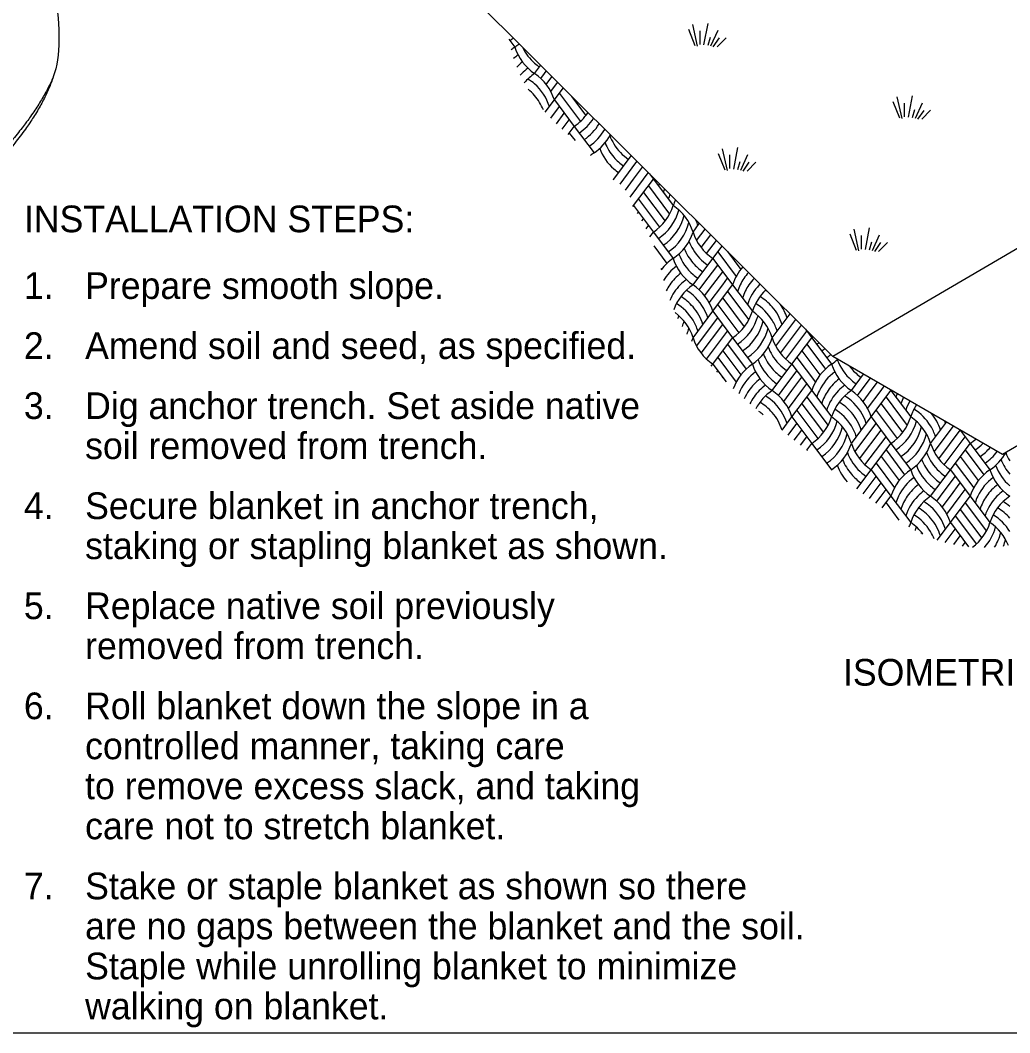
# Model space of a CAD drawing. Extents: x 99862 to 103151, y 100000 to 102076.
# Drawn here: x 100962 to 101704, y 100000 to 100758 of the extents above; entities that cross this region are included whole.
import ezdxf

# ---------------------------------------------------------------- set-up
doc = ezdxf.new("R2010")
doc.units = 0
for name, color, linetype in [('Level 1', 7, 'Continuous'), ('Level 2', 7, 'Continuous'), ('Level 20', 7, 'Continuous'), ('Level 3', 7, 'Continuous'), ('Level 31', 7, 'Continuous')]:
    doc.layers.add(name, color=color, linetype=linetype)

msp = doc.modelspace()

# ---------------------------------------------------------------- linework, layer by layer
at = {"layer": 'Level 1'}
for p, q in [((102742.49, 101035.83), (101698.37, 100433.01)), ((102103.79, 100817.24), (101571.09, 100506.49))]:
    msp.add_line(p, q, dxfattribs=at)
msp.add_lwpolyline([(99862, 99999.5), (103151, 99999.5), (103151, 102075.5), (99862, 102075.5)], close=True, dxfattribs=at)
for points in [[(100787.82, 101286.48), (101571.09, 100506.49)], [(101698.37, 100433.01), (101571.09, 100506.49)]]:
    msp.add_lwpolyline(points, dxfattribs=at)
at = {"layer": 'Level 2'}
for points, degree in [([(100901.77, 101124.83), (101009.66, 100986.39), (100961.48, 100855.3), (100998.83, 100747.61), (100986.43, 100715.92)], 3), ([(100986.43, 100715.92), (100969.49, 100664.49), (100884.41, 100595.03)], 2), ([(100986.42, 100715.89), (100965.62, 100667.43), (100887.77, 100603.87)], 2)]:
    msp.add_open_spline(points, degree=degree, dxfattribs=at)
at = {"layer": 'Level 3'}
for p, q in [((101328.27, 100744.14), (101332.66, 100738.27)), ((101347.51, 100718.47), (101352, 100724.45)), ((101354.94, 100718.47), (101356.25, 100720.22)), ((101352.17, 100714.78), (101354.94, 100718.47)), ((101356.24, 100710.32), (101360.5, 100715.99)), ((101359.69, 100705.01), (101364.75, 100711.76)), ((101362.36, 100698.67), (101369, 100707.53)), ((101366.08, 100703.62), (101381.87, 100682.57)), ((101355.54, 100689.57), (101362.36, 100698.67)), ((101362.36, 100698.67), (101377.21, 100678.87)), ((101375.17, 100701.4), (101385.94, 100687.03)), ((101359.63, 100685.13), (101366.08, 100693.72)), ((101363.86, 100680.87), (101369.79, 100688.77)), ((101368.22, 100676.79), (101373.5, 100683.82)), ((101372.65, 100672.8), (101377.21, 100678.87)), ((101373.5, 100673.92), (101377.81, 100668.18)), ((101377.21, 100678.87), (101392.06, 100659.08)), ((101406.91, 100639.28), (101420.03, 100656.77)), ((101414.34, 100639.28), (101424.28, 100652.54)), ((101421.76, 100639.28), (101428.53, 100648.31)), ((101429.18, 100639.28), (101432.79, 100644.08)), ((101433.66, 100643.21), (101436.61, 100639.28)), ((101411.56, 100635.58), (101414.34, 100639.28)), ((101415.64, 100631.12), (101421.76, 100639.28)), ((101419.09, 100625.81), (101429.18, 100639.28)), ((101421.76, 100619.48), (101436.61, 100639.28)), ((101436.61, 100639.28), (101451.46, 100619.48)), ((101429.18, 100629.38), (101445.34, 100607.84)), ((101432.9, 100634.33), (101448.78, 100613.14)), ((101425.47, 100624.43), (101441.26, 100603.37)), ((101421.27, 100618.83), (101421.76, 100619.48)), ((101421.76, 100619.48), (101436.61, 100599.68)), ((101424.7, 100613.5), (101425.47, 100614.53)), ((101427.98, 100607.97), (101429.18, 100609.58)), ((101466.31, 100599.68), (101471.05, 100606.01)), ((101431.08, 100602.2), (101432.9, 100604.63)), ((101433.99, 100596.19), (101436.61, 100599.68)), ((101436.61, 100599.68), (101451.46, 100579.88)), ((101468.98, 100593.34), (101475.31, 100601.78)), ((101472.43, 100588.04), (101479.56, 100597.55)), ((101476.5, 100583.57), (101483.81, 100593.32)), ((101436.91, 100589.38), (101446.8, 100576.19)), ((101481.16, 100579.88), (101488.06, 100589.09)), ((101484.87, 100584.83), (101498.68, 100566.41)), ((101492.15, 100585.03), (101502.12, 100571.72)), ((101466.31, 100560.08), (101481.16, 100579.88)), ((101473.73, 100560.08), (101484.87, 100574.93)), ((101481.16, 100579.88), (101496.01, 100560.08)), ((101442.2, 100572.42), (101442.73, 100571.72)), ((101481.16, 100560.08), (101488.58, 100569.98)), ((101470.96, 100556.39), (101473.73, 100560.08)), ((101475.04, 100551.92), (101481.16, 100560.08)), ((101478.48, 100546.61), (101488.58, 100560.08)), ((101481.16, 100540.28), (101496.01, 100560.08)), ((101488.58, 100560.08), (101492.29, 100565.03)), ((101496.01, 100560.08), (101510.86, 100540.28)), ((101492.29, 100555.13), (101508.18, 100533.95)), ((101484.87, 100545.23), (101500.66, 100524.18)), ((101488.58, 100550.18), (101504.74, 100528.64)), ((101466.31, 100520.48), (101481.16, 100540.28)), ((101481.16, 100540.28), (101496.01, 100520.48)), ((101525.7, 100520.48), (101539.09, 100538.33)), ((101468.98, 100514.15), (101484.87, 100535.33)), ((101472.43, 100508.84), (101488.58, 100530.38)), ((101528.38, 100514.15), (101543.34, 100534.1)), ((101531.82, 100508.84), (101547.59, 100529.87)), ((101476.5, 100504.38), (101492.29, 100525.43)), ((101535.9, 100504.38), (101551.69, 100525.43)), ((101550.64, 100526.84), (101555.4, 100520.48)), ((101481.16, 100500.68), (101496.01, 100520.48)), ((101492.29, 100515.53), (101506.2, 100496.99)), ((101496.01, 100520.48), (101510.86, 100500.68)), ((101540.55, 100500.68), (101555.4, 100520.48)), ((101551.69, 100515.53), (101565.6, 100496.99)), ((101555.4, 100520.48), (101570.25, 100500.68)), ((101488.58, 100510.58), (101502.12, 100492.53)), ((101547.98, 100510.58), (101561.52, 100492.53)), ((101480.05, 100499.2), (101481.16, 100500.68)), ((101481.16, 100500.68), (101491.07, 100487.46)), ((101484.87, 100505.63), (101498.68, 100487.22)), ((101525.7, 100480.88), (101540.55, 100500.68)), ((101540.55, 100500.68), (101555.4, 100480.88)), ((101544.27, 100505.63), (101558.08, 100487.22)), ((101484.11, 100494.72), (101484.87, 100495.73)), ((101533.13, 100480.88), (101544.27, 100495.73)), ((101585.1, 100480.88), (101594.27, 100493.11)), ((101488.24, 100490.33), (101488.58, 100490.78)), ((101540.55, 100480.88), (101547.98, 100490.78)), ((101547.98, 100480.88), (101551.69, 100485.83)), ((101592.53, 100480.88), (101599.45, 100490.12)), ((101599.95, 100480.88), (101604.63, 100487.13)), ((101607.38, 100480.88), (101609.81, 100484.13)), ((101530.36, 100477.19), (101533.13, 100480.88)), ((101534.44, 100472.73), (101540.55, 100480.88)), ((101537.88, 100467.42), (101547.98, 100480.88)), ((101540.55, 100461.09), (101555.4, 100480.88)), ((101551.69, 100475.93), (101567.58, 100454.75)), ((101555.4, 100480.88), (101570.25, 100461.09)), ((101589.76, 100477.19), (101592.53, 100480.88)), ((101593.83, 100472.73), (101599.95, 100480.88)), ((101597.28, 100467.42), (101607.38, 100480.88)), ((101599.95, 100461.09), (101614.8, 100480.88)), ((101611.09, 100475.93), (101626.97, 100454.75)), ((101614.31, 100481.54), (101614.8, 100480.88)), ((101614.8, 100480.88), (101629.65, 100461.09)), ((101547.98, 100470.98), (101564.13, 100449.44)), ((101607.38, 100470.98), (101623.53, 100449.44)), ((101533.07, 100451.1), (101540.55, 100461.09)), ((101540.55, 100461.09), (101555.4, 100441.29)), ((101544.27, 100466.04), (101560.06, 100444.98)), ((101585.1, 100441.29), (101599.95, 100461.09)), ((101599.95, 100461.09), (101614.8, 100441.29)), ((101603.66, 100466.04), (101619.45, 100444.98)), ((101537.68, 100447.35), (101544.27, 100456.14)), ((101587.78, 100434.95), (101603.66, 100456.14)), ((101644.5, 100441.29), (101656.44, 100457.21)), ((101647.17, 100434.95), (101661.62, 100454.22)), ((101542.29, 100443.6), (101547.98, 100451.19)), ((101546.93, 100439.89), (101551.69, 100446.24)), ((101591.22, 100429.64), (101607.38, 100451.19)), ((101595.3, 100425.18), (101611.09, 100446.24)), ((101650.62, 100429.64), (101666.77, 100451.19)), ((101654.69, 100425.18), (101670.48, 100446.24)), ((101666.69, 100451.3), (101674.2, 100441.29)), ((101551.59, 100436.21), (101555.4, 100441.29)), ((101555.4, 100441.29), (101570.25, 100421.49)), ((101599.95, 100421.49), (101614.8, 100441.29)), ((101614.8, 100441.29), (101629.65, 100421.49)), ((101659.35, 100421.49), (101674.2, 100441.29)), ((101674.2, 100441.29), (101689.05, 100421.49)), ((101551.69, 100436.34), (101552.07, 100435.84)), ((101607.38, 100431.39), (101620.92, 100413.33)), ((101611.09, 100436.34), (101625, 100417.79)), ((101666.77, 100431.39), (101680.31, 100413.33)), ((101670.48, 100436.34), (101684.39, 100417.79)), ((101603.66, 100426.44), (101617.47, 100408.02)), ((101663.06, 100426.44), (101676.87, 100408.02)), ((101589.15, 100407.08), (101599.95, 100421.49)), ((101593.87, 100403.49), (101603.66, 100416.54)), ((101599.95, 100421.49), (101614.8, 100401.69)), ((101644.5, 100401.69), (101659.35, 100421.49)), ((101651.92, 100401.69), (101663.06, 100416.54)), ((101659.35, 100421.49), (101674.2, 100401.69)), ((101599.95, 100401.69), (101607.38, 100411.59)), ((101659.35, 100401.69), (101666.77, 100411.59)), ((101598.62, 100399.92), (101599.95, 100401.69)), ((101603.43, 100396.43), (101607.38, 100401.69)), ((101607.38, 100401.69), (101611.09, 100406.64)), ((101608.23, 100392.93), (101614.8, 100401.69)), ((101614.8, 100401.69), (101629.65, 100381.89)), ((101649.15, 100397.99), (101651.92, 100401.69)), ((101653.23, 100393.53), (101659.35, 100401.69)), ((101656.67, 100388.22), (101666.77, 100401.69)), ((101659.35, 100381.89), (101674.2, 100401.69)), ((101666.77, 100401.69), (101670.48, 100406.64)), ((101674.2, 100401.69), (101689.05, 100381.89)), ((101611.09, 100396.74), (101620.77, 100383.83)), ((101670.48, 100396.74), (101686.37, 100375.56)), ((101663.06, 100386.84), (101678.85, 100365.78)), ((101666.77, 100391.79), (101682.93, 100370.25)), ((101649.53, 100368.81), (101659.35, 100381.89)), ((101659.35, 100381.89), (101673, 100363.68)), ((101655.56, 100366.93), (101663.06, 100376.94)), ((101661.83, 100365.4), (101666.77, 100371.99)), ((101668.39, 100364.24), (101670.48, 100367.04))]:
    msp.add_line(p, q, dxfattribs=at)
for centre, start, end in [((101307.99, 100774.41), 303.90361, 308.45036), ((101353.62, 100707.08), 123.90361, 129.17019), ((101311.7, 100769.46), 303.90361, 309.8163), ((101368.47, 100749.66), 197.6434, 236.09639), ((101372.19, 100754.61), 206.58173, 228.95992), ((101357.34, 100702.13), 126.30625, 132.85134), ((101361.05, 100697.18), 127.1006, 135.84623), ((101364.76, 100692.23), 126.331, 135.71278), ((101372.19, 100754.61), 228.95986, 236.09639), ((101364.76, 100692.23), 135.71269, 138.11289), ((101368.47, 100687.28), 123.90361, 139.77526), ((101322.84, 100682.33), 48.95968, 58.54646), ((101326.55, 100687.28), 17.6434, 56.09634), ((101319.13, 100677.38), 40.94134, 51.22081), ((101322.84, 100682.33), 17.6434, 48.95975), ((101319.13, 100677.38), 21.65425, 40.94141), ((101356.25, 100710.06), 303.90361, 326.19289), ((101359.96, 100705.11), 303.90361, 327.58033), ((101363.68, 100700.16), 303.90361, 328.97521), ((101367.39, 100695.21), 303.90361, 330.3785), ((101371.1, 100690.26), 303.90361, 331.79122), ((101435.3, 100680.36), 201.43438, 220.94161), ((101439.01, 100685.31), 200.87781, 211.33197), ((101439.01, 100685.31), 211.33188, 236.09639), ((101413.02, 100627.89), 123.90361, 129.01031), ((101431.58, 100675.41), 200.24322, 228.95992), ((101435.3, 100680.36), 220.94154, 236.09639), ((101431.58, 100675.41), 228.95986, 236.09639), ((101427.87, 100608.09), 123.90361, 125.19259), ((101472.42, 100627.89), 161.14901, 162.3566), ((101476.13, 100622.94), 159.64705, 162.3566), ((101479.84, 100617.99), 158.16286, 162.3566), ((101483.56, 100613.04), 156.69484, 162.3566), ((101487.27, 100608.09), 155.24152, 162.3566), ((101415.65, 100630.87), 303.90361, 342.3566), ((101419.36, 100625.92), 303.90361, 345.01126), ((101430.5, 100588.29), 17.6434, 56.09639), ((101423.07, 100620.97), 303.90361, 346.31988), ((101426.79, 100616.02), 303.90361, 345.77133), ((101434.21, 100593.24), 17.6434, 23.96429), ((101430.5, 100611.07), 303.90361, 342.3566), ((101502.12, 100611.07), 197.64354, 236.09639), ((101498.41, 100606.12), 200.87781, 211.33197), ((101490.98, 100596.22), 200.24322, 228.95992), ((101494.69, 100601.17), 201.43438, 220.94161), ((101498.41, 100606.12), 211.33188, 236.09639), ((101472.42, 100548.69), 123.90361, 142.90795), ((101487.27, 100591.27), 197.6434, 236.09639), ((101494.69, 100601.17), 220.94154, 236.09639), ((101476.13, 100543.74), 126.30625, 148.35357), ((101479.84, 100538.79), 127.1006, 145.49109), ((101490.98, 100596.22), 228.95986, 236.09639), ((101531.82, 100548.69), 138.53358, 162.3566), ((101535.53, 100543.74), 137.17365, 154.2266), ((101479.84, 100538.79), 145.49102, 153.23504), ((101483.56, 100533.84), 135.71269, 157.26402), ((101487.27, 100528.89), 123.90361, 160.52095), ((101483.56, 100533.84), 126.331, 135.71278), ((101445.35, 100528.89), 17.6434, 56.09634), ((101535.53, 100543.74), 154.22654, 162.3566), ((101539.24, 100538.79), 145.49102, 162.3566), ((101542.95, 100533.84), 135.71269, 162.3566), ((101539.24, 100538.79), 135.81486, 145.49109), ((101542.95, 100533.84), 134.45644, 135.71278), ((101441.63, 100523.94), 48.95968, 58.54646), ((101441.63, 100523.94), 17.6434, 48.95975), ((101546.67, 100528.89), 133.09758, 162.3566), ((101501.03, 100523.94), 54.86941, 58.54646), ((101434.21, 100514.04), 31.33163, 58.48737), ((101437.92, 100518.99), 40.94134, 59.30215), ((101493.61, 100514.04), 31.33163, 58.48737), ((101497.32, 100518.99), 40.94134, 59.30215), ((101501.03, 100523.94), 17.6434, 35.42771), ((101430.5, 100509.09), 17.6434, 53.56336), ((101419.36, 100546.72), 341.67956, 345.01126), ((101437.92, 100518.99), 17.6434, 40.94141), ((101475.05, 100551.67), 303.90361, 342.3566), ((101478.76, 100546.72), 303.90361, 345.01126), ((101489.89, 100509.09), 17.6434, 56.09639), ((101497.32, 100518.99), 17.6434, 40.94141), ((101423.07, 100541.77), 339.95462, 346.31988), ((101434.21, 100514.04), 17.6434, 31.33172), ((101482.47, 100541.77), 303.90361, 346.31988), ((101493.61, 100514.04), 17.6434, 31.33172), ((101426.79, 100536.82), 338.78338, 345.77133), ((101486.18, 100536.82), 303.90361, 345.77133), ((101430.5, 100531.87), 338.13682, 342.3566), ((101502.12, 100531.87), 197.64354, 236.09639), ((101489.89, 100531.87), 303.90361, 342.3566), ((101561.51, 100531.87), 197.64354, 236.09639), ((101534.44, 100551.67), 303.90361, 305.67726), ((101538.15, 100546.72), 303.90361, 307.05181), ((101554.09, 100521.97), 201.43438, 220.94161), ((101557.8, 100526.92), 200.87781, 211.33197), ((101557.8, 100526.92), 211.33188, 236.09639), ((101541.87, 100541.77), 303.90361, 308.42167), ((101545.58, 100536.82), 303.90361, 309.78769), ((101531.82, 100469.49), 123.90361, 160.21914), ((101546.67, 100512.07), 197.6434, 236.09639), ((101550.38, 100517.02), 200.24322, 228.95992), ((101591.21, 100469.49), 123.90361, 162.3566), ((101549.29, 100531.87), 303.90361, 312.84825), ((101606.06, 100512.07), 197.6434, 236.09639), ((101609.77, 100517.02), 200.24322, 228.95992), ((101613.49, 100521.97), 217.06181, 220.94161), ((101535.53, 100464.55), 126.30625, 154.2266), ((101554.09, 100521.97), 220.94154, 236.09639), ((101594.93, 100464.55), 126.30625, 154.2266), ((101613.49, 100521.97), 220.94154, 236.09639), ((101539.24, 100459.6), 127.1006, 145.49109), ((101542.95, 100454.65), 126.331, 135.71278), ((101550.38, 100517.02), 228.95986, 236.09639), ((101598.64, 100459.6), 127.1006, 145.49109), ((101602.35, 100454.65), 126.331, 135.71278), ((101609.77, 100517.02), 228.95986, 236.09639), ((101535.53, 100464.55), 154.22654, 158.46675), ((101539.24, 100459.6), 145.49102, 156.52144), ((101542.95, 100454.65), 135.71269, 154.46379), ((101546.67, 100449.7), 123.90361, 152.31021), ((101501.03, 100444.75), 48.95968, 58.54646), ((101504.74, 100449.7), 17.6434, 56.09634), ((101594.93, 100464.55), 154.22654, 162.3566), ((101598.64, 100459.6), 145.49102, 162.3566), ((101602.35, 100454.65), 135.71269, 162.3566), ((101606.06, 100449.7), 123.90361, 162.3566), ((101560.43, 100444.75), 48.95968, 58.54646), ((101564.14, 100449.7), 17.6434, 56.09634), ((101650.61, 100469.49), 161.85684, 162.3566), ((101654.32, 100464.55), 158.09342, 162.3566), ((101658.03, 100459.6), 154.36495, 162.3566), ((101497.32, 100439.8), 40.94134, 59.30215), ((101501.03, 100444.75), 17.6434, 48.95975), ((101556.72, 100439.8), 40.94134, 59.30215), ((101560.43, 100444.75), 17.6434, 48.95975), ((101661.75, 100454.65), 150.65493, 162.3566), ((101665.46, 100449.7), 146.94767, 162.3566), ((101493.61, 100434.85), 47.8159, 53.85927), ((101497.32, 100439.8), 17.6434, 40.94141), ((101534.44, 100472.47), 303.90361, 342.3566), ((101549.29, 100429.9), 17.6434, 56.09639), ((101553, 100434.85), 31.33163, 58.48737), ((101556.72, 100439.8), 17.6434, 40.94141), ((101593.84, 100472.47), 303.90361, 342.3566), ((101608.69, 100429.9), 17.6434, 56.09639), ((101612.4, 100434.85), 31.33163, 58.48737), ((101616.11, 100439.8), 17.6434, 39.71565), ((101538.15, 100467.53), 303.90361, 345.01126), ((101541.87, 100462.58), 303.90361, 346.31988), ((101553, 100434.85), 17.6434, 31.33172), ((101597.55, 100467.53), 303.90361, 345.01126), ((101601.26, 100462.58), 303.90361, 346.31988), ((101612.4, 100434.85), 17.6434, 31.33172), ((101619.83, 100444.75), 17.6434, 20.761), ((101545.58, 100457.63), 303.90361, 345.77133), ((101604.98, 100457.63), 303.90361, 345.77133), ((101549.29, 100452.68), 303.90361, 342.3566), ((101620.91, 100452.68), 197.64354, 236.09639), ((101608.69, 100452.68), 303.90361, 342.3566), ((101680.31, 100452.68), 197.64354, 236.09639), ((101653.24, 100472.47), 303.90361, 311.99561), ((101656.95, 100467.53), 303.90361, 315.85295), ((101660.66, 100462.58), 303.90361, 319.6458), ((101617.2, 100447.73), 200.87781, 211.33197), ((101676.6, 100447.73), 200.87781, 211.33197), ((101664.37, 100457.63), 303.90361, 323.39324), ((101668.09, 100452.68), 303.90361, 331.09805), ((101735.99, 100447.73), 200.87781, 211.33197), ((101609.77, 100437.83), 200.24322, 222.36299), ((101613.49, 100442.78), 201.43438, 220.94161), ((101617.2, 100447.73), 211.33188, 236.09639), ((101669.17, 100437.83), 200.24322, 228.95992), ((101672.88, 100442.78), 201.43438, 220.94161), ((101676.6, 100447.73), 211.33188, 236.09639), ((101728.57, 100437.83), 200.24322, 228.95992), ((101732.28, 100442.78), 201.43438, 220.94161), ((101606.06, 100432.88), 197.6434, 197.65262), ((101591.21, 100390.3), 123.90361, 123.90903), ((101613.49, 100442.78), 220.94154, 236.09639), ((101650.61, 100390.3), 123.90361, 162.3566), ((101654.32, 100385.35), 126.30625, 154.2266), ((101665.46, 100432.88), 197.6434, 236.09639), ((101672.88, 100442.78), 220.94154, 236.09639), ((101710.01, 100390.3), 123.90361, 162.3566), ((101713.72, 100385.35), 126.30625, 154.2266), ((101724.86, 100432.88), 197.6434, 236.09639), ((101658.03, 100380.4), 127.1006, 145.49109), ((101669.17, 100437.83), 228.95986, 236.09639), ((101717.43, 100380.4), 127.1006, 145.49109), ((101654.32, 100385.35), 154.22654, 162.3566), ((101658.03, 100380.4), 145.49102, 162.3566), ((101661.75, 100375.45), 135.71269, 162.3566), ((101665.46, 100370.5), 123.90361, 162.3566), ((101661.75, 100375.45), 126.331, 135.71278), ((101623.54, 100370.5), 17.6434, 56.09634), ((101713.72, 100385.35), 154.22654, 162.3566), ((101717.43, 100380.4), 145.49102, 162.3566), ((101721.14, 100375.45), 135.71269, 162.3566), ((101724.86, 100370.5), 123.90361, 162.3566), ((101721.14, 100375.45), 126.331, 135.71278), ((101616.11, 100360.6), 40.94134, 59.30215), ((101619.83, 100365.55), 48.95968, 58.54646), ((101619.83, 100365.55), 17.6434, 48.95975), ((101675.51, 100360.6), 40.94134, 59.30215), ((101679.22, 100365.55), 48.95968, 58.54646), ((101612.4, 100355.65), 31.33163, 58.48737), ((101616.11, 100360.6), 17.6434, 40.94141), ((101671.8, 100355.65), 31.33163, 58.48737), ((101593.84, 100393.28), 337.235, 342.3566), ((101608.69, 100350.7), 36.71313, 56.09639), ((101597.55, 100388.33), 340.98108, 345.01126), ((101653.24, 100393.28), 307.40062, 342.3566), ((101656.95, 100388.33), 317.98882, 345.01126), ((101668.09, 100350.7), 22.00735, 56.09639), ((101601.26, 100383.38), 345.17399, 346.31988), ((101612.4, 100355.65), 21.79654, 31.33172), ((101660.66, 100383.38), 328.10657, 346.31988), ((101664.37, 100378.43), 337.79045, 345.77133)]:
    msp.add_arc(centre, 37.58, start, end, dxfattribs=at)
at = {"layer": 'Level 31'}
for p, q in [((101467.95, 100739.28), (101463.13, 100751.52)), ((101469.73, 100738.97), (101466.06, 100755.28)), ((101471.61, 100740.33), (101471.61, 100750.58)), ((101474.54, 100740.01), (101477.57, 100756.12)), ((101479.77, 100739.17), (101485.1, 100750.89)), ((101477.57, 100739.7), (101479.35, 100745.76)), ((101481.55, 100738.55), (101486.15, 100745.14)), ((101484.48, 100738.55), (101491.07, 100745.24)), ((101621.37, 100685.02), (101616.56, 100697.26)), ((101623.15, 100684.71), (101619.49, 100701.03)), ((101625.03, 100686.07), (101625.03, 100696.32)), ((101627.96, 100685.76), (101630.99, 100701.87)), ((101633.19, 100684.92), (101638.53, 100696.64)), ((101630.99, 100685.44), (101632.77, 100691.51)), ((101634.97, 100684.29), (101639.57, 100690.88)), ((101637.9, 100684.29), (101644.49, 100690.99)), ((101490.32, 100646.14), (101485.5, 100658.38)), ((101492.09, 100645.83), (101488.43, 100662.15)), ((101496.91, 100646.87), (101499.94, 100662.98)), ((101493.98, 100647.19), (101493.98, 100657.44)), ((101499.94, 100646.56), (101501.72, 100652.63)), ((101502.14, 100646.04), (101507.47, 100657.75)), ((101503.92, 100645.41), (101508.52, 100652)), ((101506.84, 100645.41), (101513.44, 100652.11)), ((101589.02, 100585.88), (101584.21, 100598.12)), ((101590.8, 100585.57), (101587.14, 100601.89)), ((101595.61, 100586.62), (101598.65, 100602.73)), ((101600.84, 100585.78), (101606.18, 100597.5)), ((101592.68, 100586.93), (101592.68, 100597.18)), ((101598.65, 100586.3), (101600.43, 100592.37)), ((101602.62, 100585.15), (101607.23, 100591.74)), ((101605.55, 100585.15), (101612.14, 100591.85))]:
    msp.add_line(p, q, dxfattribs=at)

# ---------------------------------------------------------------- texts
at = {"layer": 'Level 20'}
for s, p in [('INSTALLATION STEPS:', (100964.43, 100599.54)), ('1.', (100964.43, 100549.54)), ('Prepare smooth slope.', (101010.34, 100549.54)), ('2.', (100964.43, 100504.54)), ('Amend soil and seed, as specified.', (101010.34, 100504.54)), ('3.', (100964.43, 100459.54)), ('Dig anchor trench. Set aside native ', (101010.34, 100459.54)), ('soil removed from trench.', (101010.34, 100429.54)), ('4.', (100964.43, 100384.54)), ('Secure blanket in anchor trench,', (101010.34, 100384.54)), ('staking or stapling blanket as shown.', (101010.34, 100354.54)), ('5.', (100964.43, 100309.54)), ('Replace native soil previously ', (101010.34, 100309.54)), ('removed from trench.', (101010.34, 100279.54)), ('ISOMETRIC VIEW', (101578.77, 100259.68)), ('6.', (100964.43, 100234.54)), ('Roll blanket down the slope in a ', (101010.34, 100234.54)), ('controlled manner, taking care', (101010.34, 100204.54)), ('to remove excess slack, and taking', (101010.34, 100174.54)), ('care not to stretch blanket.', (101010.34, 100144.54)), ('7.', (100964.43, 100099.54)), ('Stake or staple blanket as shown so there ', (101010.34, 100099.54)), ('are no gaps between the blanket and the soil.', (101010.34, 100069.54)), ('Staple while unrolling blanket to minimize', (101010.34, 100039.54)), ('walking on blanket.', (101010.34, 100009.54))]:
    msp.add_text(s, height=20, dxfattribs=at).set_placement(p)

doc.saveas('drawing.dxf')
